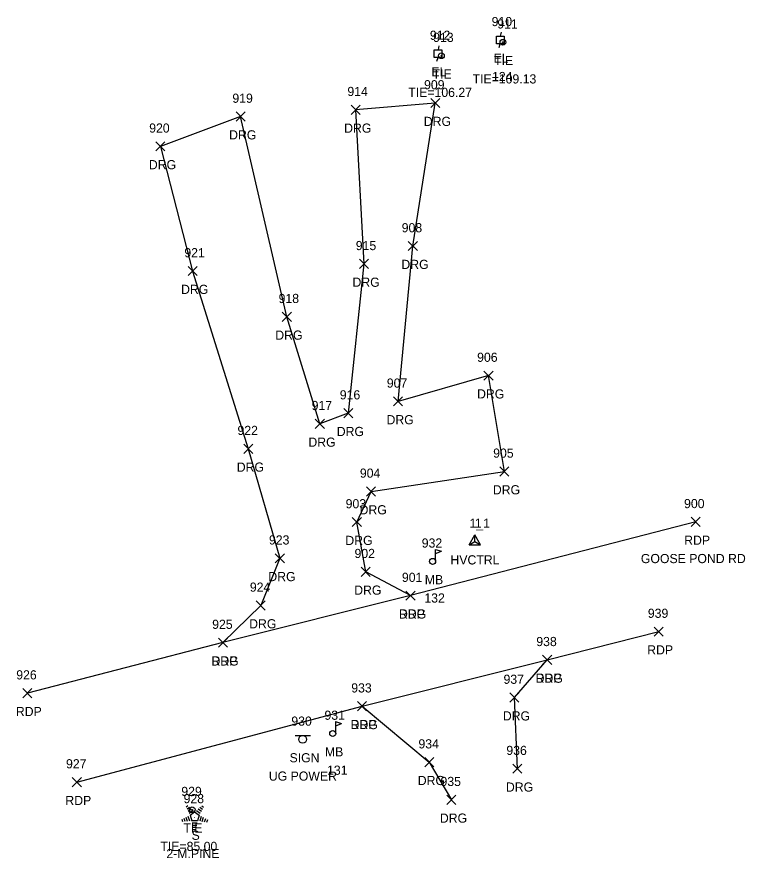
# Model space of a CAD drawing. Extents: x 1514253 to 1516033, y 782541 to 785002.
# Drawn here: x 1515402.2 to 1515561.1, y 784817.9 to 785001.5 of the extents above; entities that cross this region are included whole.
import ezdxf

# ---------------------------------------------------------------- set-up
doc = ezdxf.new("R2010")
doc.units = 0
for name, color, linetype in [('C_A', 7, 'Continuous'), ('C_C', 7, 'Continuous'), ('C_I', 7, 'Continuous'), ('CBP', 7, 'Continuous'), ('CPSM', 7, 'Continuous'), ('L_A', 7, 'Continuous'), ('L_C', 7, 'Continuous'), ('L_I', 7, 'Continuous'), ('LMB', 7, 'Continuous'), ('LTC', 7, 'Continuous'), ('P_A', 7, 'Continuous'), ('P_C', 7, 'Continuous'), ('P_I', 7, 'Continuous'), ('P_TIC', 7, 'Continuous'), ('PET', 7, 'Continuous'), ('R_A', 7, 'Continuous'), ('R_I', 7, 'Continuous'), ('R_TIC', 7, 'Continuous'), ('RDG', 7, 'Continuous'), ('S_A', 7, 'Continuous'), ('S_C', 7, 'Continuous'), ('S_I', 7, 'Continuous'), ('SSGN', 7, 'Continuous'), ('U_A', 7, 'Continuous'), ('U_C', 7, 'Continuous'), ('U_I', 7, 'Continuous'), ('UEPT', 7, 'Continuous')]:
    doc.layers.add(name, color=color, linetype=linetype)

msp = doc.modelspace()

# ---------------------------------------------------------------- linework, layer by layer
at = {"layer": 'CBP'}
for centre, radius in [((1515508.25, 784995.99), 0.625), ((1515508.25, 784995.99), 0.0833), ((1515494.83, 784993.05), 0.625), ((1515494.83, 784993.05), 0.0833), ((1515440.46, 784828.49), 0.625), ((1515440.46, 784828.49), 0.0833)]:
    msp.add_circle(centre, radius, dxfattribs=at)
at = {"layer": 'CPSM'}
for p, q in [((1515500.86, 784886.3), (1515502.11, 784888.47)), ((1515503.36, 784886.3), (1515502.11, 784888.47)), ((1515502.11, 784887.02), (1515502.11, 784888.47)), ((1515500.86, 784886.3), (1515502.11, 784888.46)), ((1515500.86, 784886.3), (1515502.11, 784887.02)), ((1515500.86, 784886.3), (1515502.11, 784887.02)), ((1515503.36, 784886.3), (1515502.11, 784888.46)), ((1515502.11, 784887.02), (1515502.11, 784888.46)), ((1515502.11, 784887.02), (1515502.11, 784887.02)), ((1515502.11, 784887.02), (1515503.36, 784886.3)), ((1515502.11, 784887.02), (1515502.11, 784887.02)), ((1515502.11, 784887.02), (1515503.36, 784886.3)), ((1515500.86, 784886.3), (1515503.36, 784886.3)), ((1515500.86, 784886.3), (1515503.36, 784886.3))]:
    msp.add_line(p, q, dxfattribs=at)
at = {"layer": 'LMB'}
for p, q in [((1515493.55, 784885.3), (1515494.85, 784884.92)), ((1515493.56, 784882.71), (1515493.56, 784885.31)), ((1515493.56, 784884.4), (1515494.84, 784884.91)), ((1515492.9, 784882.7), (1515492.9, 784882.7)), ((1515471.76, 784847.72), (1515473.05, 784847.34)), ((1515471.77, 784845.13), (1515471.77, 784847.72)), ((1515471.77, 784846.82), (1515473.05, 784847.33)), ((1515471.11, 784845.12), (1515471.11, 784845.12))]:
    msp.add_line(p, q, dxfattribs=at)
for centre in [(1515492.9, 784882.7), (1515471.11, 784845.12)]:
    msp.add_circle(centre, 0.656, dxfattribs=at)
at = {"layer": 'LTC'}
for p, q in [((1515439.14, 784829.13), (1515439.49, 784829.38)), ((1515439.35, 784828.66), (1515439.88, 784829.04)), ((1515439.56, 784828.19), (1515440.26, 784828.71)), ((1515439.77, 784827.73), (1515440.64, 784828.37)), ((1515439.99, 784827.27), (1515441, 784828.01)), ((1515441, 784828.01), (1515442, 784827.28)), ((1515441.42, 784828.32), (1515442.23, 784827.73)), ((1515441.79, 784828.67), (1515442.47, 784828.18)), ((1515442.16, 784829.02), (1515442.71, 784828.62)), ((1515442.53, 784829.37), (1515442.95, 784829.06)), ((1515438.17, 784826.41), (1515438.32, 784825.94)), ((1515438.62, 784826.62), (1515438.84, 784825.97)), ((1515439.08, 784826.84), (1515439.35, 784826)), ((1515439.54, 784827.05), (1515439.87, 784826.04)), ((1515439.99, 784827.27), (1515440.38, 784826.08)), ((1515441.61, 784826.08), (1515440.38, 784826.08)), ((1515442, 784827.28), (1515441.61, 784826.08)), ((1515442.44, 784827.01), (1515442.1, 784825.97)), ((1515442.88, 784826.76), (1515442.59, 784825.88)), ((1515443.33, 784826.51), (1515443.09, 784825.78)), ((1515443.77, 784826.26), (1515443.58, 784825.69)), ((1515441.57, 784825.58), (1515440.42, 784825.58)), ((1515441.49, 784825.08), (1515440.5, 784825.08)), ((1515441.4, 784824.58), (1515440.57, 784824.58)), ((1515441.32, 784824.08), (1515440.64, 784824.08))]:
    msp.add_line(p, q, dxfattribs=at)
at = {"layer": 'P_TIC'}
for points in [[(1515549.3, 784890.31), (1515551.3, 784892.31)], [(1515551.3, 784890.31), (1515549.3, 784892.31)], [(1515487.08, 784874.21), (1515489.08, 784876.21)], [(1515489.08, 784874.21), (1515487.08, 784876.21)], [(1515541.23, 784866.37), (1515543.23, 784868.37)], [(1515543.23, 784866.37), (1515541.23, 784868.37)], [(1515446.18, 784863.96), (1515448.18, 784865.96)], [(1515448.18, 784863.96), (1515446.18, 784865.96)], [(1515516.89, 784860.2), (1515518.89, 784862.2)], [(1515518.89, 784860.2), (1515516.89, 784862.2)], [(1515403.5, 784852.93), (1515405.5, 784854.93)], [(1515405.5, 784852.93), (1515403.5, 784854.93)], [(1515476.52, 784850.08), (1515478.52, 784852.08)], [(1515478.52, 784850.08), (1515476.52, 784852.08)], [(1515414.3, 784833.52), (1515416.3, 784835.52)], [(1515416.3, 784833.52), (1515414.3, 784835.52)]]:
    msp.add_lwpolyline(points, dxfattribs=at)
at = {"layer": 'PET'}
for points in [[(1515550.3, 784891.31), (1515488.08, 784875.21), (1515447.18, 784864.96), (1515404.5, 784853.93)], [(1515415.3, 784834.52), (1515477.52, 784851.08), (1515517.89, 784861.2), (1515542.23, 784867.37)]]:
    msp.add_lwpolyline(points, dxfattribs=at)
at = {"layer": 'R_TIC'}
for points in [[(1515475.12, 784980.25), (1515477.12, 784982.25)], [(1515477.12, 784980.25), (1515475.12, 784982.25)], [(1515492.5, 784981.72), (1515494.5, 784983.72)], [(1515494.5, 784981.72), (1515492.5, 784983.72)], [(1515450.03, 784978.78), (1515452.03, 784980.78)], [(1515452.03, 784978.78), (1515450.03, 784980.78)], [(1515432.52, 784972.27), (1515434.52, 784974.27)], [(1515434.52, 784972.27), (1515432.52, 784974.27)], [(1515487.61, 784950.51), (1515489.61, 784952.51)], [(1515489.61, 784950.51), (1515487.61, 784952.51)], [(1515476.94, 784946.62), (1515478.94, 784948.62)], [(1515478.94, 784946.62), (1515476.94, 784948.62)], [(1515439.55, 784945.06), (1515441.55, 784947.06)], [(1515441.55, 784945.06), (1515439.55, 784947.06)], [(1515460.11, 784935.07), (1515462.11, 784937.07)], [(1515462.11, 784935.07), (1515460.11, 784937.07)], [(1515504.12, 784922.24), (1515506.12, 784924.24)], [(1515506.12, 784922.24), (1515504.12, 784924.24)], [(1515484.36, 784916.61), (1515486.36, 784918.61)], [(1515486.36, 784916.61), (1515484.36, 784918.61)], [(1515473.51, 784914.04), (1515475.51, 784916.04)], [(1515475.51, 784914.04), (1515473.51, 784916.04)], [(1515467.32, 784911.71), (1515469.32, 784913.71)], [(1515469.32, 784911.71), (1515467.32, 784913.71)], [(1515451.7, 784906.27), (1515453.7, 784908.27)], [(1515453.7, 784906.27), (1515451.7, 784908.27)], [(1515507.56, 784901.32), (1515509.56, 784903.32)], [(1515509.56, 784901.32), (1515507.56, 784903.32)], [(1515478.48, 784896.95), (1515480.48, 784898.95)], [(1515480.48, 784896.95), (1515478.48, 784898.95)], [(1515475.38, 784890.27), (1515477.38, 784892.27)], [(1515477.38, 784890.27), (1515475.38, 784892.27)], [(1515458.58, 784882.37), (1515460.58, 784884.37)], [(1515460.58, 784882.37), (1515458.58, 784884.37)], [(1515477.31, 784879.42), (1515479.31, 784881.42)], [(1515479.31, 784879.42), (1515477.31, 784881.42)], [(1515487.08, 784874.21), (1515489.08, 784876.21)], [(1515489.08, 784874.21), (1515487.08, 784876.21)], [(1515454.4, 784872.07), (1515456.4, 784874.07)], [(1515456.4, 784872.07), (1515454.4, 784874.07)], [(1515446.18, 784863.96), (1515448.18, 784865.96)], [(1515448.18, 784863.96), (1515446.18, 784865.96)], [(1515516.89, 784860.2), (1515518.89, 784862.2)], [(1515518.89, 784860.2), (1515516.89, 784862.2)], [(1515509.74, 784851.97), (1515511.74, 784853.97)], [(1515511.74, 784851.97), (1515509.74, 784853.97)], [(1515476.52, 784850.08), (1515478.52, 784852.08)], [(1515478.52, 784850.08), (1515476.52, 784852.08)], [(1515491.19, 784837.87), (1515493.19, 784839.87)], [(1515493.19, 784837.87), (1515491.19, 784839.87)], [(1515510.41, 784836.44), (1515512.41, 784838.44)], [(1515512.41, 784836.44), (1515510.41, 784838.44)], [(1515496, 784829.66), (1515498, 784831.66)], [(1515498, 784829.66), (1515496, 784831.66)]]:
    msp.add_lwpolyline(points, dxfattribs=at)
at = {"layer": 'RDG'}
for points in [[(1515488.08, 784875.21), (1515478.31, 784880.42), (1515476.38, 784891.27), (1515479.48, 784897.95), (1515508.56, 784902.32), (1515505.12, 784923.24), (1515485.36, 784917.61), (1515488.61, 784951.51), (1515493.5, 784982.72), (1515476.12, 784981.25), (1515477.94, 784947.62), (1515474.51, 784915.04), (1515468.32, 784912.71), (1515461.11, 784936.07), (1515451.03, 784979.78), (1515433.52, 784973.27), (1515440.55, 784946.06), (1515452.7, 784907.27), (1515459.58, 784883.37), (1515455.4, 784873.07), (1515447.18, 784864.96)], [(1515511.41, 784837.44), (1515510.74, 784852.97), (1515517.89, 784861.2)], [(1515477.52, 784851.08), (1515492.19, 784838.87), (1515497, 784830.66)]]:
    msp.add_lwpolyline(points, dxfattribs=at)
at = {"layer": 'SSGN'}
for p, q in [((1515462.92, 784844.68), (1515466.25, 784844.68)), ((1515464.56, 784843.85), (1515464.56, 784843.85))]:
    msp.add_line(p, q, dxfattribs=at)
msp.add_circle((1515464.56, 784843.85), 0.833, dxfattribs=at)
at = {"layer": 'UEPT'}
for p, q in [((1515506.84, 784995.67), (1515506.84, 784997.34)), ((1515506.84, 784997.34), (1515508.5, 784997.34)), ((1515507.84, 784998.17), (1515507.67, 784997.34)), ((1515508.5, 784997.34), (1515508.5, 784995.67)), ((1515494.27, 784995.18), (1515494.11, 784994.35)), ((1515508.5, 784995.67), (1515506.84, 784995.67)), ((1515507.42, 784994.84), (1515507.67, 784995.67)), ((1515507.67, 784996.51), (1515507.67, 784996.51)), ((1515493.27, 784992.68), (1515493.27, 784994.35)), ((1515493.27, 784994.35), (1515494.94, 784994.35)), ((1515494.11, 784993.52), (1515494.11, 784993.52)), ((1515494.94, 784994.35), (1515494.94, 784992.68)), ((1515494.94, 784992.68), (1515493.27, 784992.68)), ((1515493.86, 784991.85), (1515494.11, 784992.68))]:
    msp.add_line(p, q, dxfattribs=at)

# ---------------------------------------------------------------- texts
at = {"layer": 'C_A'}
for s, p in [('TIE', (1515506.32, 784990.99)), ('TIE', (1515492.91, 784988.05)), ('HVCTRL', (1515496.8, 784882.03)), ('HVCTRL', (1515496.8, 784882.02)), ('TIE', (1515438.54, 784823.49))]:
    msp.add_text(s, height=2, dxfattribs=at).set_placement(p)
at = {"layer": 'C_C'}
for s, p in [('TIE=109.13', (1515501.63, 784986.99)), ('TIE=106.27', (1515487.6, 784984.05)), ('TIE=85.00', (1515433.52, 784819.49))]:
    msp.add_text(s, height=2, dxfattribs=at).set_placement(p)
at = {"layer": 'C_I'}
for s, p in [('911', (1515507.02, 784998.99)), ('913', (1515493.03, 784996.05)), ('1_1', (1515500.96, 784890.02)), ('1', (1515502.11, 784890.03)), ('929', (1515438.09, 784831.49))]:
    msp.add_text(s, height=2, dxfattribs=at).set_placement(p)
at = {"layer": 'L_A'}
for s, p in [('MB', (1515491.21, 784877.7)), ('MB', (1515469.42, 784840.12)), ('S', (1515440.33, 784821.92))]:
    msp.add_text(s, height=2, dxfattribs=at).set_placement(p)
at = {"layer": 'L_C'}
for s, p in [('132', (1515491.11, 784873.7)), ('131', (1515469.88, 784836.12)), ('2-M.PINE', (1515434.83, 784817.92))]:
    msp.add_text(s, height=2, dxfattribs=at).set_placement(p)
at = {"layer": 'L_I'}
for s, p in [('932', (1515490.54, 784885.7)), ('931', (1515469.32, 784848.12)), ('928', (1515438.58, 784829.92))]:
    msp.add_text(s, height=2, dxfattribs=at).set_placement(p)
at = {"layer": 'LTC'}
msp.add_text('.', height=1.04, rotation=270, dxfattribs=at).set_placement((1515440.88, 784827.02))
at = {"layer": 'P_A'}
for p in [(1515547.79, 784886.31), (1515485.57, 784870.21), (1515539.72, 784862.37), (1515444.67, 784859.96), (1515515.38, 784856.2), (1515401.99, 784848.93), (1515475.01, 784846.08), (1515412.79, 784829.52)]:
    msp.add_text('RDP', height=2, dxfattribs=at).set_placement(p)
at = {"layer": 'P_C'}
msp.add_text('GOOSE POND RD', height=2, dxfattribs=at).set_placement((1515538.34, 784882.31))
at = {"layer": 'P_I'}
for s, p in [('900', (1515547.77, 784894.31)), ('901', (1515486.21, 784878.21)), ('939', (1515539.86, 784870.37)), ('925', (1515444.82, 784867.96)), ('938', (1515515.53, 784864.2)), ('926', (1515402.08, 784856.93)), ('933', (1515475.16, 784854.08)), ('927', (1515412.94, 784837.52))]:
    msp.add_text(s, height=2, dxfattribs=at).set_placement(p)
at = {"layer": 'R_A'}
for p in [(1515490.99, 784977.72), (1515448.52, 784974.78), (1515473.61, 784976.25), (1515431.01, 784968.27), (1515486.1, 784946.51), (1515475.43, 784942.62), (1515438.04, 784941.06), (1515458.59, 784931.07), (1515502.61, 784918.24), (1515482.85, 784912.61), (1515472, 784910.04), (1515465.81, 784907.71), (1515450.19, 784902.27), (1515506.05, 784897.32), (1515476.97, 784892.95), (1515473.87, 784886.27), (1515457.07, 784878.37), (1515475.8, 784875.42), (1515485.57, 784870.21), (1515452.89, 784868.07), (1515444.67, 784859.96), (1515515.38, 784856.2), (1515508.23, 784847.97), (1515475.01, 784846.08), (1515489.67, 784833.87), (1515508.9, 784832.44), (1515494.49, 784825.66)]:
    msp.add_text('DRG', height=2, dxfattribs=at).set_placement(p)
at = {"layer": 'R_I'}
for s, p in [('909', (1515491.05, 784985.72)), ('914', (1515474.32, 784984.25)), ('919', (1515449.23, 784982.78)), ('920', (1515431.08, 784976.27)), ('908', (1515486.17, 784954.51)), ('921', (1515438.75, 784949.06)), ('915', (1515476.15, 784950.62)), ('918', (1515459.31, 784939.07)), ('906', (1515502.62, 784926.24)), ('907', (1515482.92, 784920.61)), ('916', (1515472.66, 784918.04)), ('917', (1515466.52, 784915.71)), ('922', (1515450.34, 784910.27)), ('905', (1515506.12, 784905.32)), ('904', (1515477.04, 784900.95)), ('903', (1515473.94, 784894.27)), ('923', (1515457.21, 784886.37)), ('902', (1515475.87, 784883.42)), ('901', (1515486.21, 784878.21)), ('924', (1515453.04, 784876.07)), ('925', (1515444.82, 784867.96)), ('938', (1515515.53, 784864.2)), ('937', (1515508.38, 784855.97)), ('933', (1515475.16, 784854.08)), ('934', (1515489.82, 784841.87)), ('936', (1515509, 784840.44)), ('935', (1515494.63, 784833.66))]:
    msp.add_text(s, height=2, dxfattribs=at).set_placement(p)
at = {"layer": 'S_A'}
msp.add_text('SIGN', height=2, dxfattribs=at).set_placement((1515461.7, 784838.83))
at = {"layer": 'S_C'}
msp.add_text('UG POWER', height=2, dxfattribs=at).set_placement((1515457.18, 784834.83))
at = {"layer": 'S_I'}
msp.add_text('930', height=2, dxfattribs=at).set_placement((1515462.09, 784846.83))
at = {"layer": 'U_A'}
for p in [(1515506.2, 784991.51), (1515492.64, 784988.52)]:
    msp.add_text('EL', height=2, dxfattribs=at).set_placement(p)
at = {"layer": 'U_C'}
msp.add_text('124', height=2, dxfattribs=at).set_placement((1515505.87, 784987.51))
at = {"layer": 'U_I'}
for s, p in [('910', (1515505.79, 784999.51)), ('912', (1515492.31, 784996.52))]:
    msp.add_text(s, height=2, dxfattribs=at).set_placement(p)

doc.saveas('drawing.dxf')
